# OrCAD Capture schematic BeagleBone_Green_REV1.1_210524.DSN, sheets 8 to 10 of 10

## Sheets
8 P09_10/100 Ethernet: size B; title: BeagleBone Green Ethernet
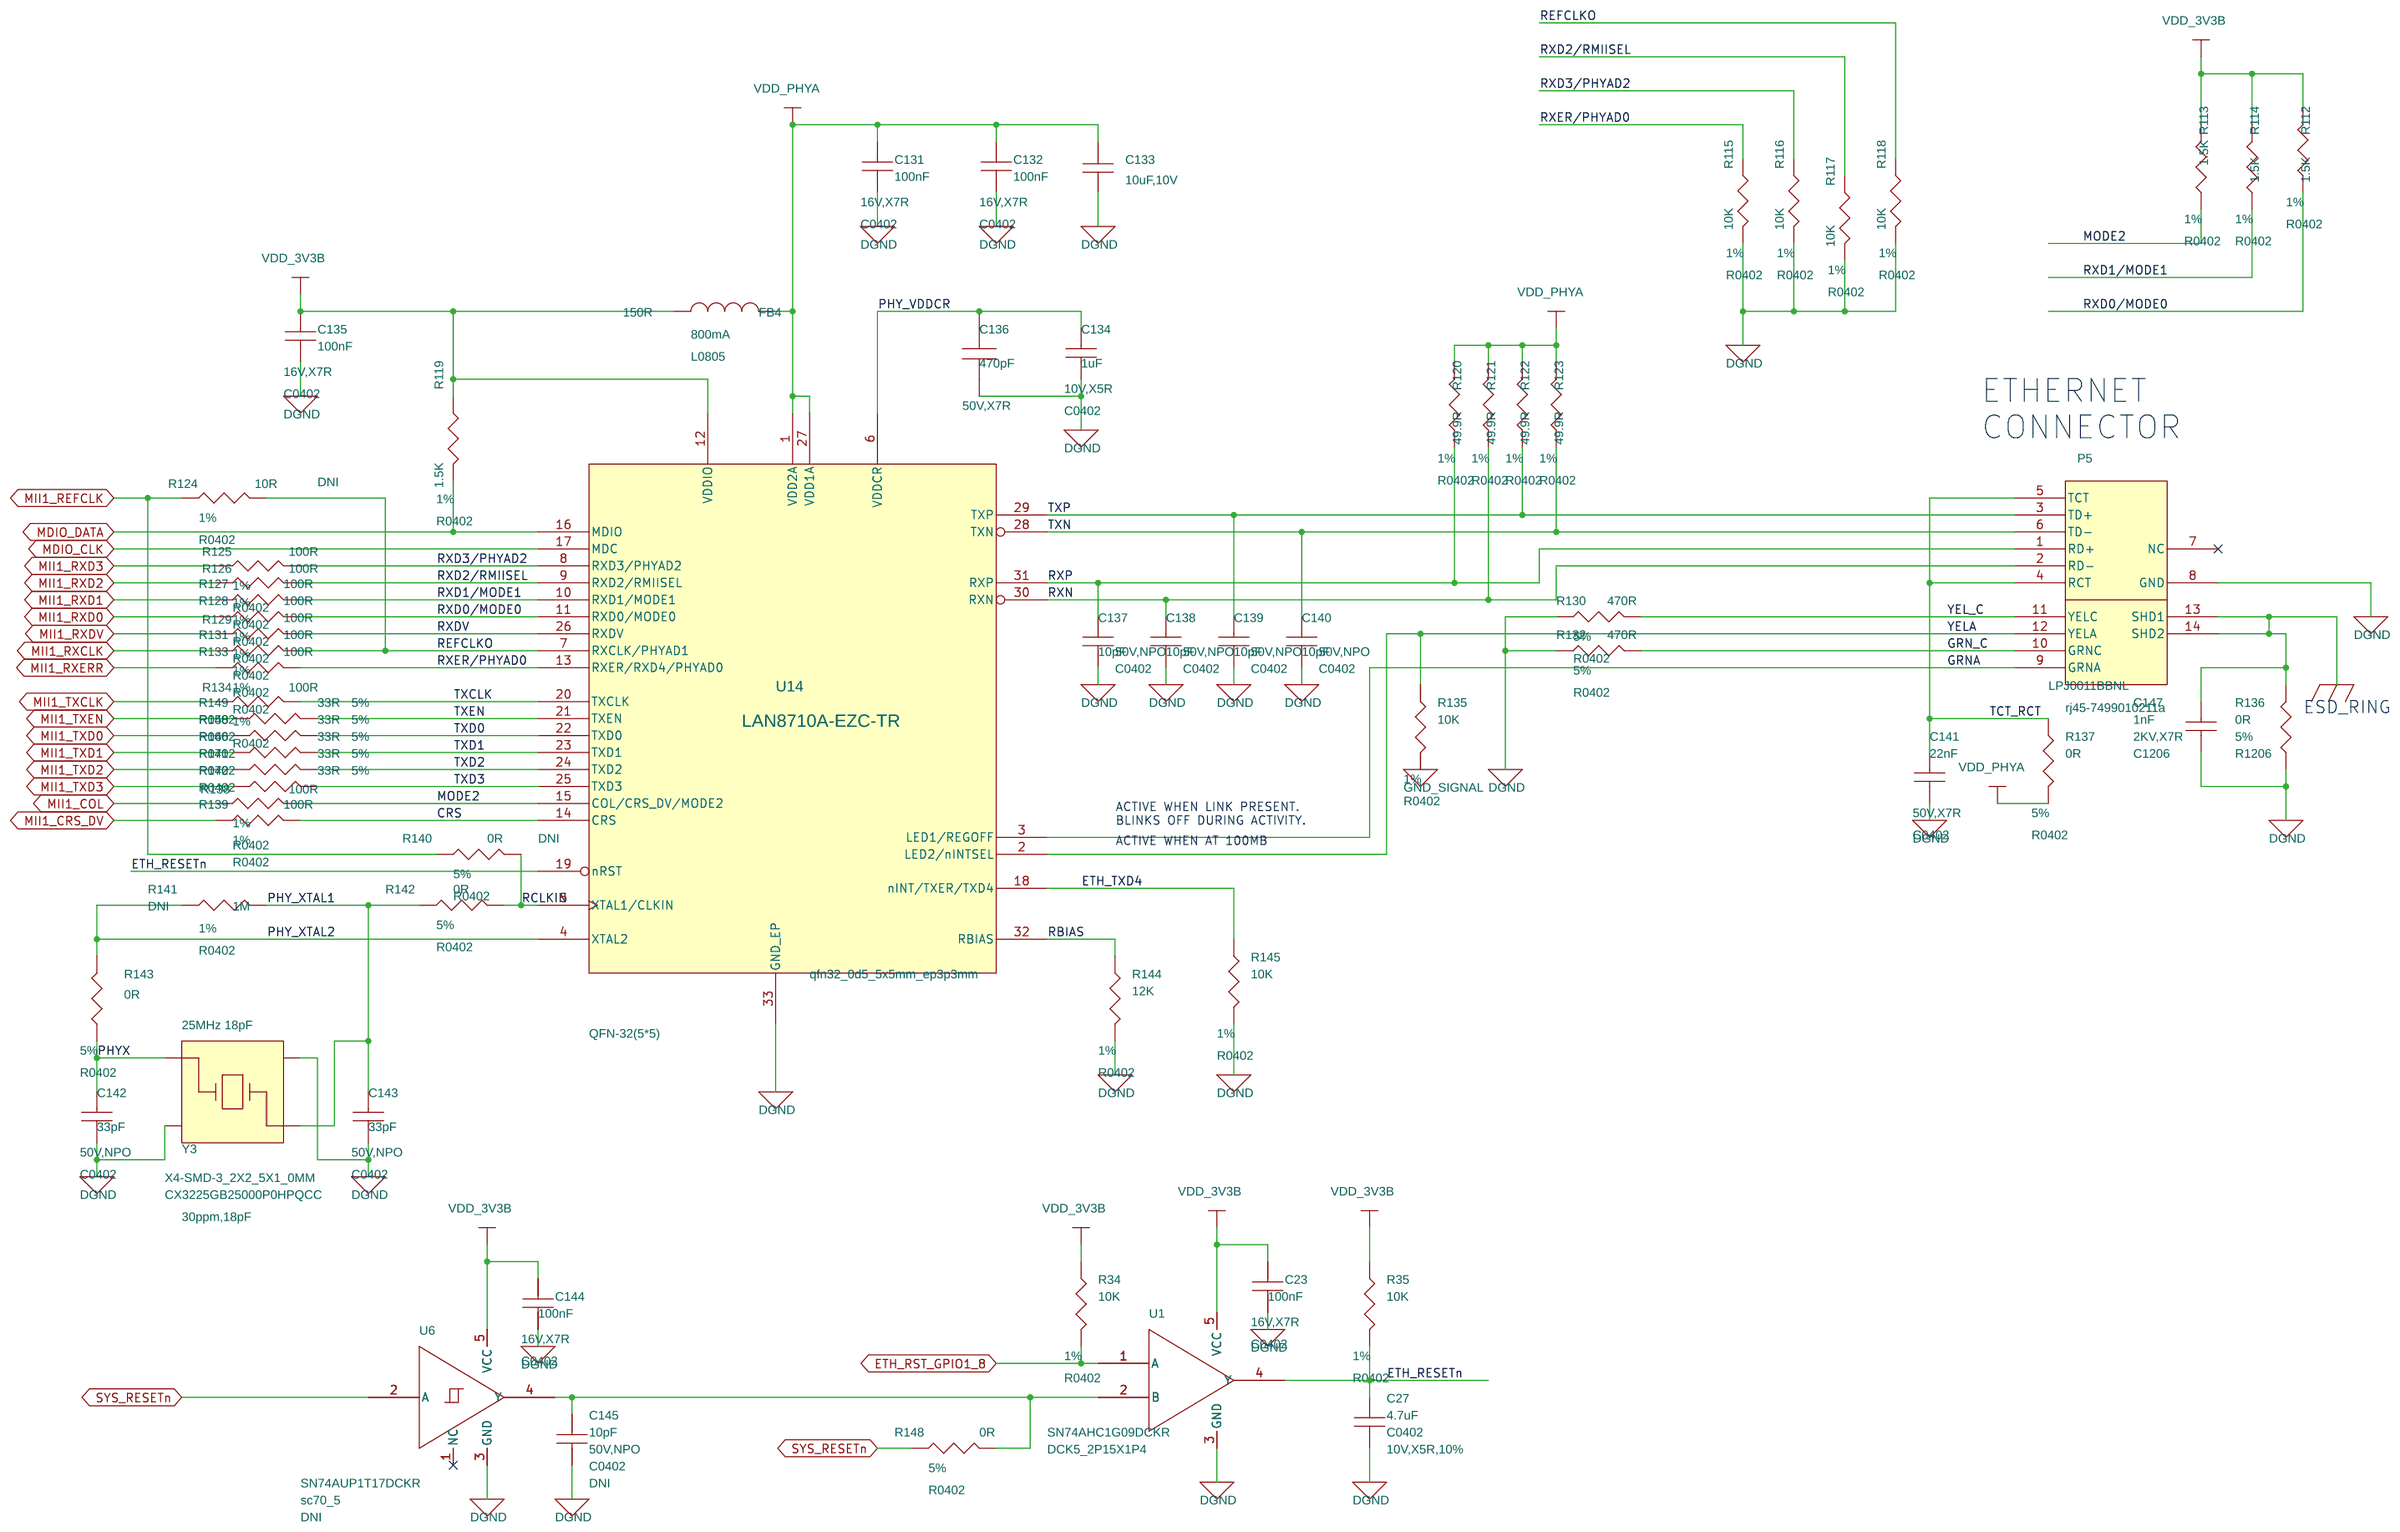
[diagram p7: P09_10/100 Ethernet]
9 P04_AM335x 2/3, USB: size C; title: BeagleBone Green Processor 2 of 3, USB,  and Serial
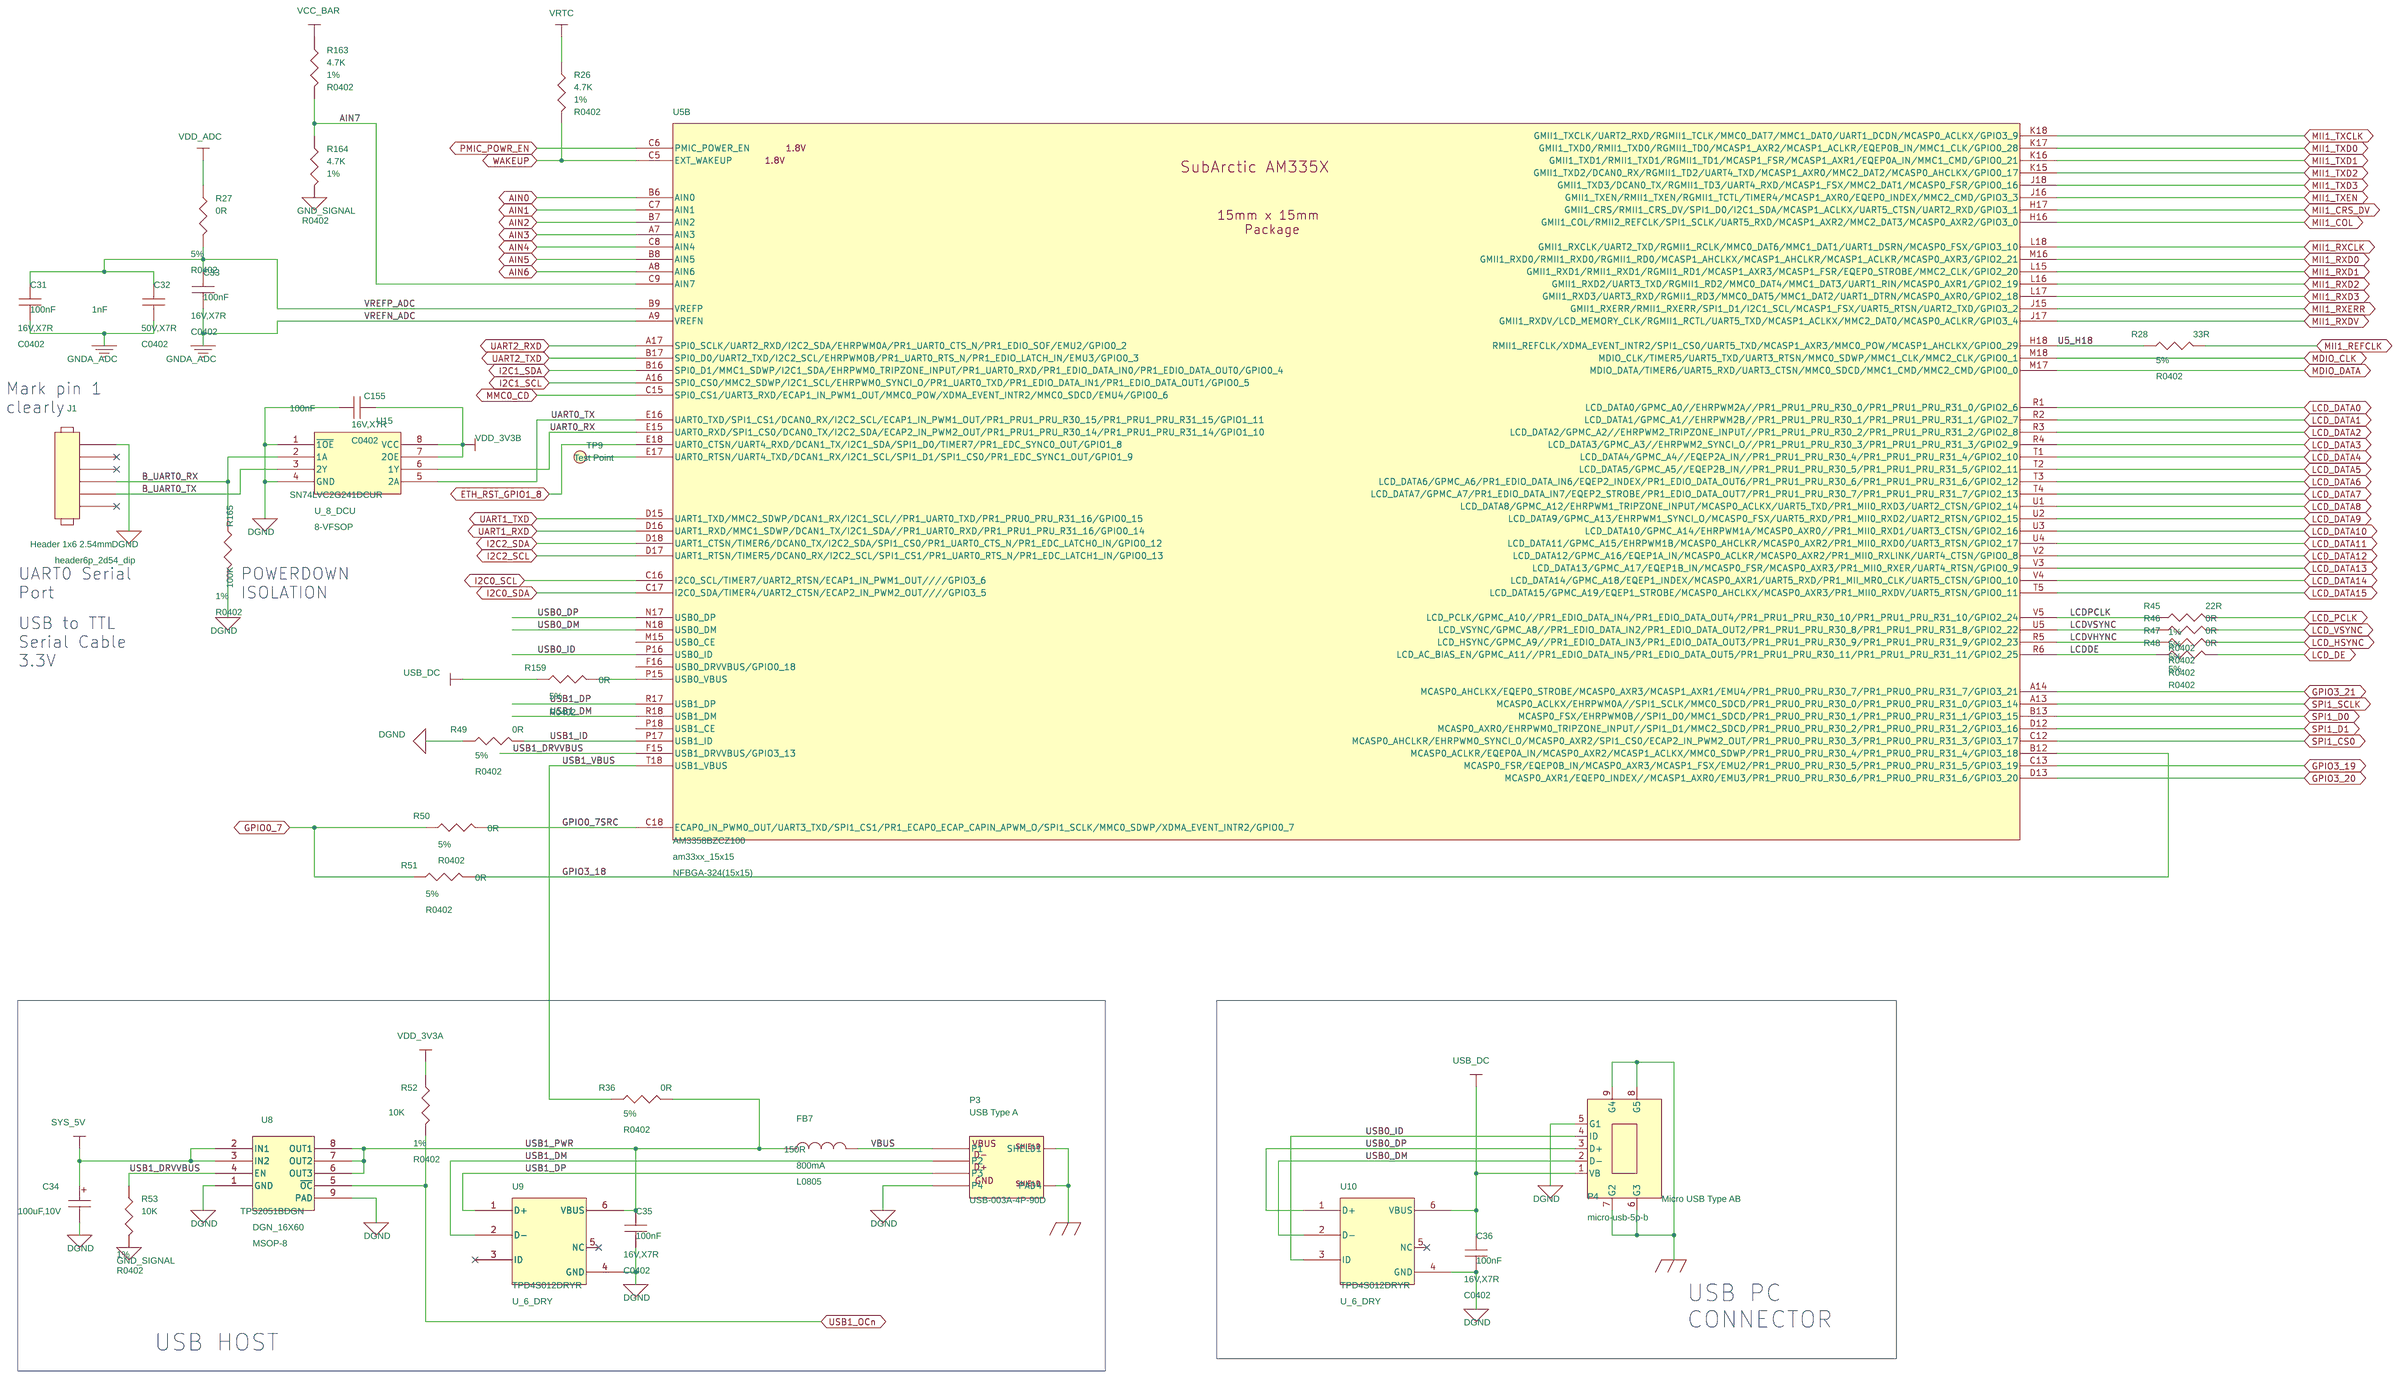
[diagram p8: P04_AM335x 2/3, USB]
10 P03_AM335x 1/3, JTAG: size C; title: BeagleBone Green Processor 1 of 3 and JTAG
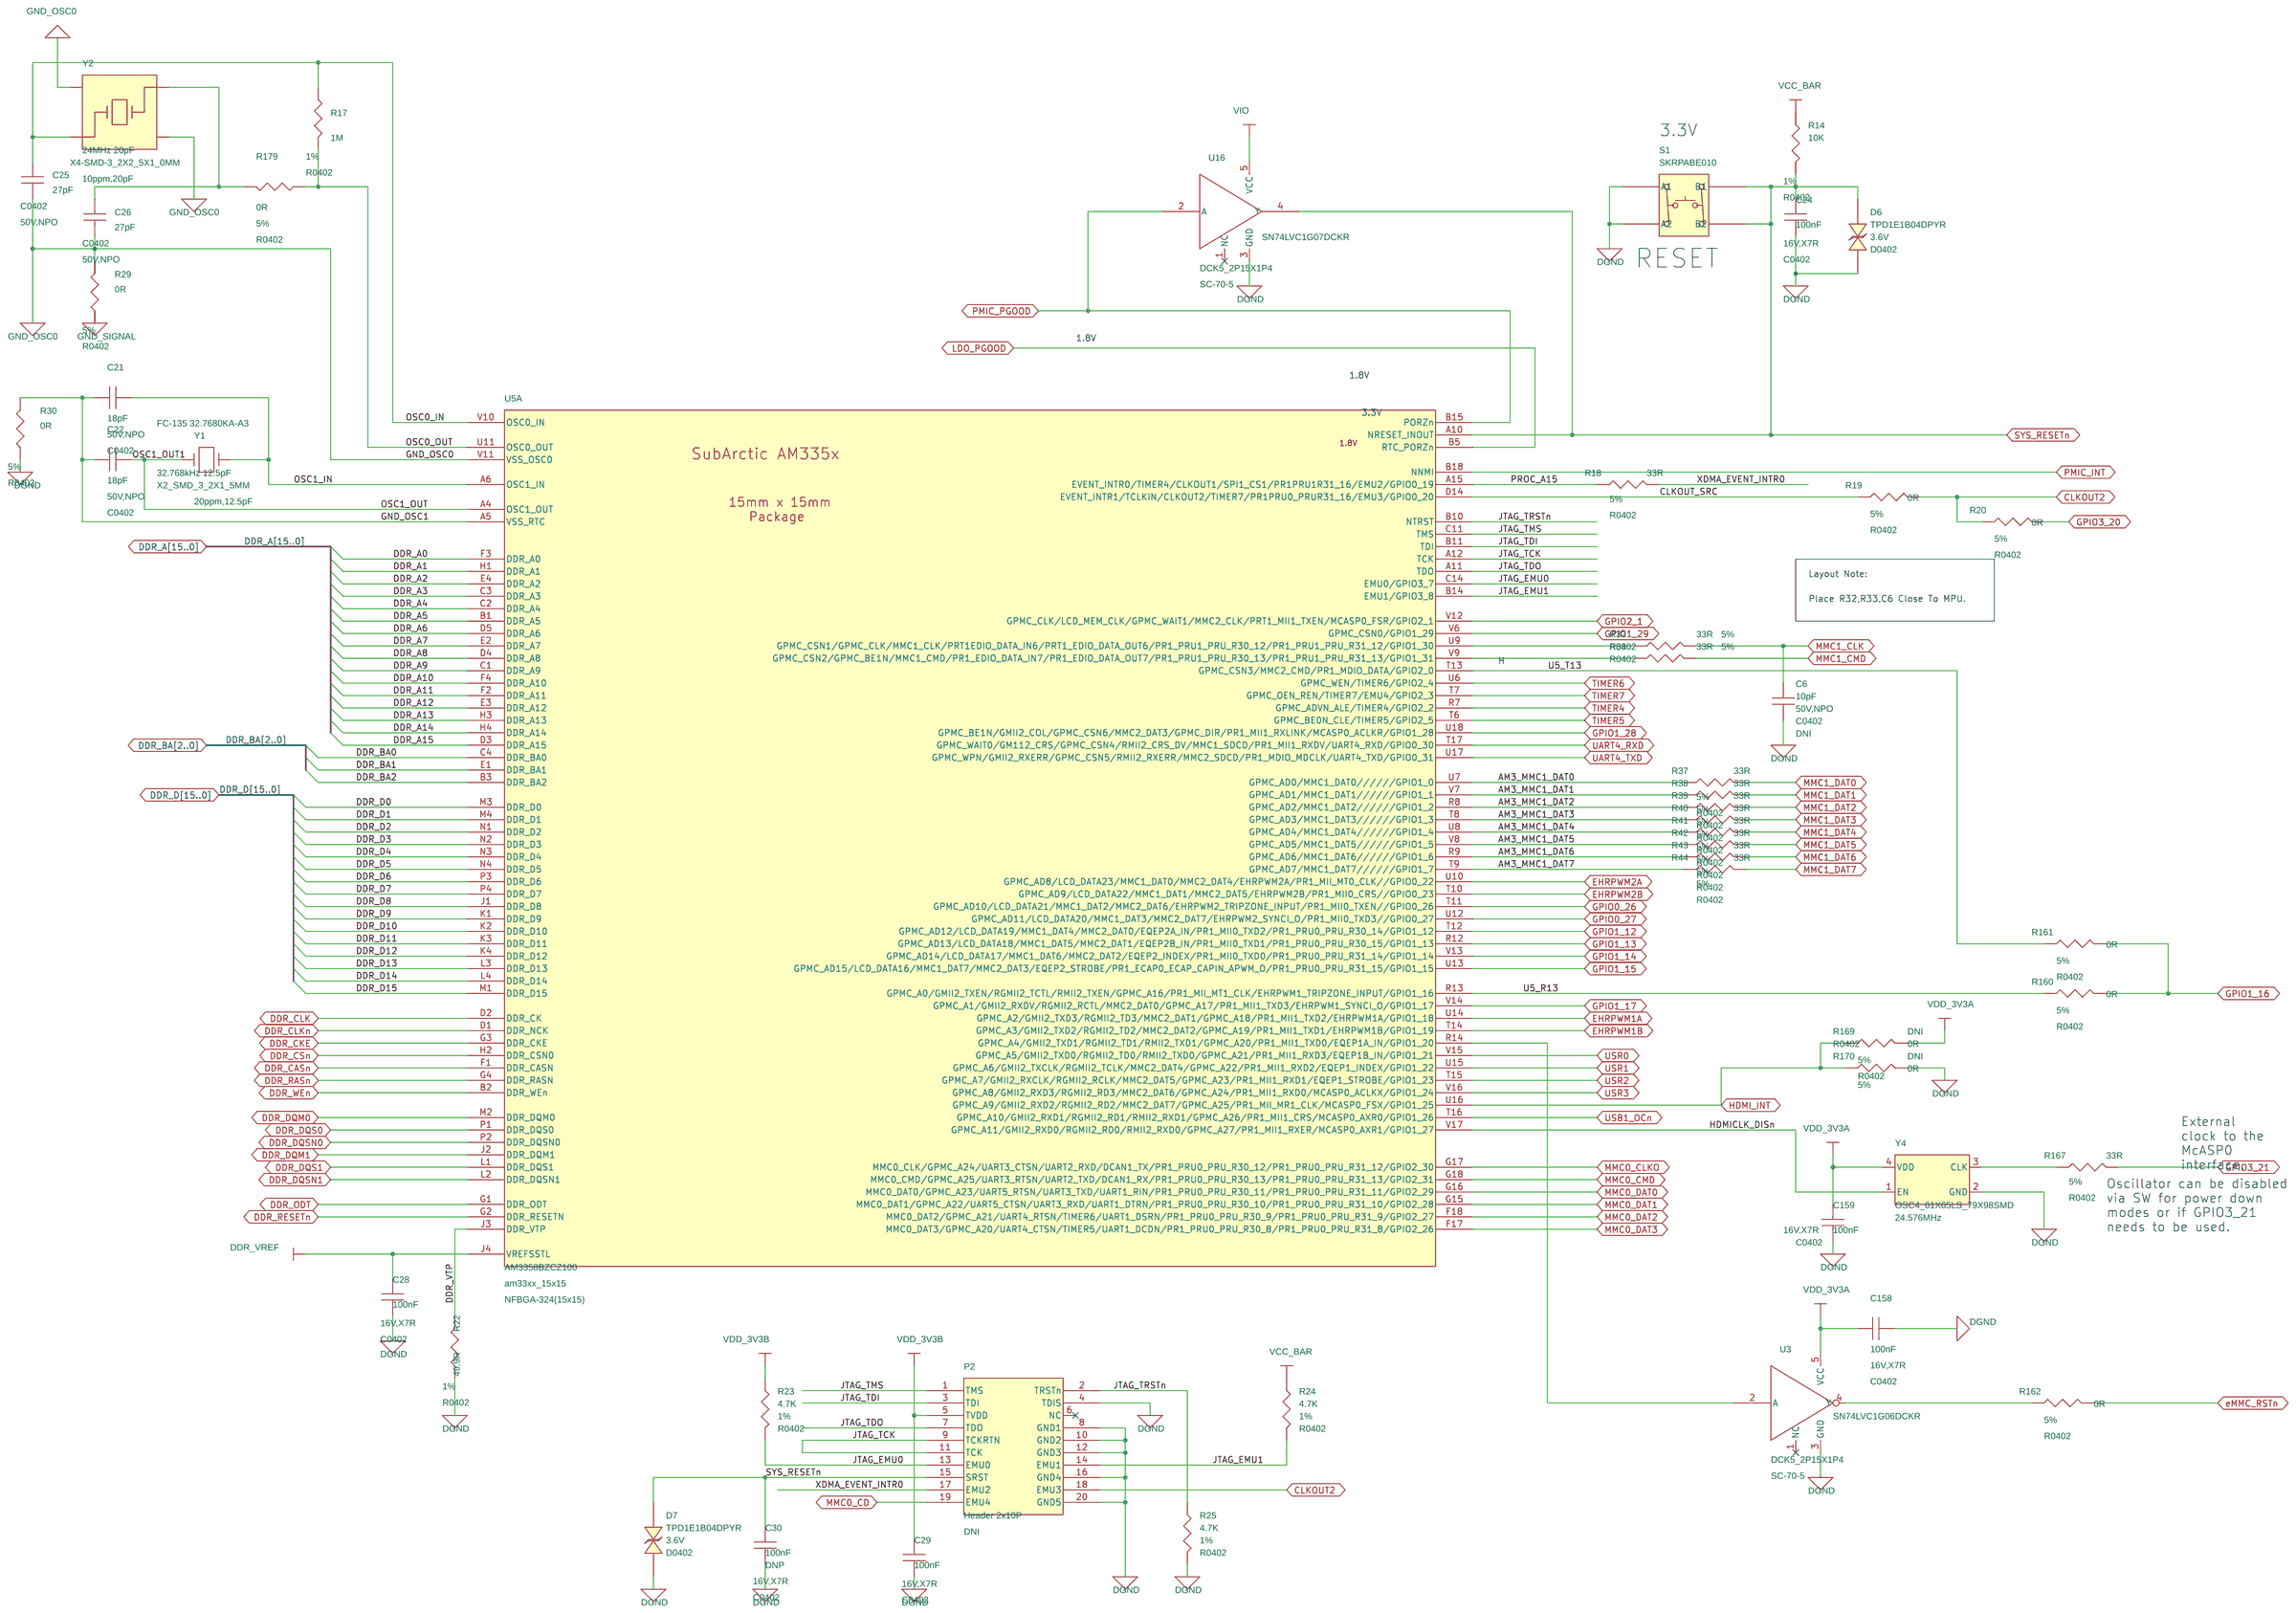
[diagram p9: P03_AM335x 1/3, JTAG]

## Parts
sheet P03_AM335x 1/3, JTAG
C6  10pF  [C0402]
C21  18pF  [C0402]
C22  18pF  [C0402]
C24  100nF  [C0402]
C25  27pF  [C0402]
C26  27pF  [C0402]
C28  100nF  [C0402]
C29  100nF  [C0402]
C30  100nF  [C0402]
C158  100nF  [C0402]
C159  100nF  [C0402]
D6  TPD1E1B04DPYR  [D0402]
D7  TPD1E1B04DPYR  [D0402]
P2  Header 2x10P  [HEADER10X2_SMD]
R14  10K  [R0402]
R17  1M  [R0402]
R18  33R  [R0402]
R19  0R  [R0402]
R20  0R  [R0402]
R22  49.9R  [R0402]
R23  4.7K  [R0402]
R24  4.7K  [R0402]
R25  4.7K  [R0402]
R29  0R  [R0402]
R30  0R  [R0402]
R32  33R  [R0402]
R33  33R  [R0402]
R37  33R  [R0402]
R38  33R  [R0402]
R39  33R  [R0402]
R40  33R  [R0402]
R41  33R  [R0402]
R42  33R  [R0402]
R43  33R  [R0402]
R44  33R  [R0402]
R160  0R  [R0402]
R161  0R  [R0402]
R162  0R  [R0402]
R167  33R  [R0402]
R169  0R  [R0402]
R170  0R  [R0402]
R179  0R  [R0402]
S1  SKRPABE010  [SW_4P]
U3  SN74LVC1G06DCKR  [DCK5_2P15X1P4]
U16  SN74LVC1G07DCKR  [DCK5_2P15X1P4]
Y1  32.768kHz 12.5pF  [X2_SMD_3_2X1_5MM]
Y2  24MHz 20pF  [X4-SMD-3_2X2_5X1_0MM]
Y4  24.576MHz  [OSC4_61X65LS_79X98SMD]
sheet P04_AM335x 2/3, USB
C31  100nF  [C0402]
C32  1nF  [C0402]
C33  100nF  [C0402]
C34  100uF,10V  [RD205SMD_250D]
C35  100nF  [C0402]
C36  100nF  [C0402]
C155  100nF  [C0402]
FB7  150R  [L0805]
J1  Header 1x6 2.54mm  [header6p_2d54_dip]
P3  USB Type A  [USB-003A-4P-90D]
P4  Micro USB Type AB  [micro-usb-5p-b]
R26  4.7K  [R0402]
R27  0R  [R0402]
R28  33R  [R0402]
R36  0R  [R0402]
R45  22R  [R0402]
R46  0R  [R0402]
R47  0R  [R0402]
R48  0R  [R0402]
R49  0R  [R0402]
R50  0R  [R0402]
R51  0R  [R0402]
R52  10K  [R0402]
R53  10K  [R0402]
R159  0R  [R0402]
R163  4.7K  [R0402]
R164  4.7K  [R0402]
R165  100K  [R0402]
TP9  Test Point  [TP60C33D]
U5  AM3358BZCZ100  [am33xx_15x15]  (sections A,B,C)
U8  TPS2051BDGN  [DGN_16X60]
U9  TPD4S012DRYR  [U_6_DRY]
U10  TPD4S012DRYR  [U_6_DRY]
U15  SN74LVC2G241DCUR  [U_8_DCU]
sheet P09_10/100 Ethernet
C23  100nF  [C0402]
C27  4.7uF  [C0402]
C131  100nF  [C0402]
C132  100nF  [C0402]
C133  10uF,10V  [805]
C134  1uF  [C0402]
C135  100nF  [C0402]
C136  470pF  [C0402]
C137  10pF  [C0402]
C138  10pF  [C0402]
C139  10pF  [C0402]
C140  10pF  [C0402]
C141  22nF  [C0402]
C142  33pF  [C0402]
C143  33pF  [C0402]
C144  100nF  [C0402]
C145  10pF  [C0402]
C147  1nF  [C1206]
FB4  150R  [L0805]
P5  LPJ0011BBNL  [rj45-7499010211a]
R34  10K  [R0402]
R35  10K  [R0402]
R112  1.5K  [R0402]
R113  1.5K  [R0402]
R114  1.5K  [R0402]
R115  10K  [R0402]
R116  10K  [R0402]
R117  10K  [R0402]
R118  10K  [R0402]
R119  1.5K  [R0402]
R120  49.9R  [R0402]
R121  49.9R  [R0402]
R122  49.9R  [R0402]
R123  49.9R  [R0402]
R124  10R  [R0402]
R125  100R  [R0402]
R126  100R  [R0402]
R127  100R  [R0402]
R128  100R  [R0402]
R129  100R  [R0402]
R130  470R  [R0402]
R131  100R  [R0402]
R132  470R  [R0402]
R133  100R  [R0402]
R134  100R  [R0402]
R135  10K  [R0402]
R136  0R  [R1206]
R137  0R  [R0402]
R138  100R  [R0402]
R139  100R  [R0402]
R140  0R  [R0402]
R141  1M  [R0402]
R142  0R  [R0402]
R143  0R  [R0402]
R144  12K  [R0402]
R145  10K  [R0402]
R148  0R  [R0402]
R149  33R  [R0402]
R158  33R  [R0402]
R166  33R  [R0402]
R171  33R  [R0402]
R172  33R  [R0402]
U1  SN74AHC1G09DCKR  [DCK5_2P15X1P4]
U6  SN74AUP1T17DCKR  [sc70_5]
U14  LAN8710A-EZC-TR  [qfn32_0d5_5x5mm_ep3p3mm]
Y3  25MHz 18pF  [X4-SMD-3_2X2_5X1_0MM]

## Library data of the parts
C6 C145 = CC: SMD CAP Ceramic 10pF-50V-5%-NPO;0402; ASSY: DNI; Manufacturer: YAGEO; Manufacturer Part Number: CC0402JRNPO9BN100; PN: 302010001; Package Size: 0402; Part Type: Ceramic; Rating: 50V,NPO; Status: BeagleBone Carrier Board; Temperature: -55°C to 125°C
C21 C22 = CAP_18PF_COG_50V_5%_0402: SMD CAP Ceramic 18pF-50V-5%-NPO;0402; Manufacturer: YAGEO; Manufacturer Part Number: CC0402JRNPO9BN180; PN: 302010016; Package Size: 0402; Part Type: Ceramic Capacitor; Rating: 50V,NPO; Status: BeagleBone Carrier Board; Temperature: -55°C to 125°C
C23 C24 C28 C29 C31 C33 C35 C36 C131 C132 C135 C144 C155 C158 C159 = CAP_0.1uF_X5R_6.3V_20%_0201: SMD CAP Ceramic 100nF-16V-10%-X7R;0402; Manufacturer: YAGEO; Manufacturer Part Number: CC0402KRX7R7BB104; PN: 302010004; Package Size: 0402; Part Type: Ceramic Capacitor; Rating: 16V,X7R; Status: BeagleBone Carrier Board; Temperature: -55°C to 125°C
C25 C26 = CC: SMD CAP Ceramic 27pF-50V-5%-NPO;0402; Manufacturer: YAGEO; Manufacturer Part Number: CC0402JRNPO9BN270; PN: 302010027; Package Size: 0402; Rating: 50V,NPO; Status: BeagleBone AI TDA4VM; Temperature: -55°C to 125°C
C30 = CAP_0.1uF_X5R_6.3V_20%_0201: SMD CAP Ceramic 100nF-16V-10%-X7R;0402; ASSY: DNP; Manufacturer: YAGEO; Manufacturer Part Number: CC0402KRX7R7BB104; PN: 302010004; Package Size: 0402; Part Type: Ceramic Capacitor; Rating: 16V,X7R; Status: BeagleBone Carrier Board; Temperature: -55°C to 125°C
D6 D7 = DIODE_TVS_BI-DIR: SMD TVS DIODE 3.6V-6.4V-1pF;X1SON(2); Manufacturer: TI; PN: 304050798; Package Size: 0402; Part Type: ESD; Rating: 3.6V; Status: Grove Base Cape for PocketBeagle; Temperature: -40°C to 125°C
P2 = HDR_10x2_CJTAG_0: SMD Black Male Header;2*10P-1.27mm; ASSY: DNI; Part Type: Male Header
R14 R34 R35 R52 R53 R135 R145 = RES_10K_1_16W_1%_0402: SMD RES 10K-1%-1/16W;0402; Manufacturer: YAGEO; Manufacturer Part Number: RC0402FR-0710KL; PN: 301010047; Package Size: 0402; Part Type: Thick Film Resistor; Rating: 1%; Status: BeagleBone Carrier Board; Temperature: -55°C to 155°C
R17 = RES_1M_1_16W_1%_0402: SMD RES 1M-1%-1/16W;0402; Manufacturer: YAGEO; Manufacturer Part Number: RC0402FR-071ML; PN: 301010043; Package Size: 0402; Part Type: Thick Film Resistor; Rating: 1%; Status: BeagleBone Carrier Board; Temperature: -55°C to 155°C
R18 R28 R167 = RES_33_0402: SMD RES 33R-5%-1/16W;0402; Manufacturer: YAGEO; Manufacturer Part Number: RC0402JR-0733RL; PN: 301010034; Package Size: 0402; Part Number: RES_33_0201; Part Type: Thick Film Resistor; Rating: 5%; Status: BeagleBone Carrier Board; Temperature: -55°C to 155°C
R19 R20 R27 R29 R30 R142 R143 R148 R179 = RES_0_1_16W_1%_0402: SMD RES 0R-5%-1/16W;0402; Manufacturer: YAGEO; Manufacturer Part Number: RC0402JR-070RL; PN: 301010000; Package Size: 0402; Part Type: Thick Film Resistor; Rating: 5%; Status: BeagleBone Carrier Board; Temperature: -55°C to 155°C
R22 R120-R123 = RES_4.7K_0402: SMD RES 49.9R-1%-1/16W;0402; Manufacturer: YAGEO; Manufacturer Part Number: RC0402FR-0749R9L; PN: 301010041; Package Size: 0402; Part Type: Thick Film Resistor; Rating: 1%; Status: BeagleBone Carrier Board; Temperature: -55°C to 155°C
R23-R26 R163 R164 = R: SMD RES;4.7K-1%-1/16W-0402; Manufacturer: YAGEO; Manufacturer Part Number: RC0402FR-074K7L; PN: 301010633; Package Size: 0402; Part Type: RES; Rating: 1%; Status: BeagleBone Carrier Board; Temperature: -55°C to 155°C
R32 R33 R149 R158 R166 R171 R172 = R: SMD RES 33R-5%-1/16W;0402; Manufacturer: YAGEO; Manufacturer Part Number: RC0402JR-0733RL; PN: 301010034; Package Size: 0402; Part Type: RES; Rating: 5%; Status: BeagleBone Carrier Board; Temperature: -55°C to 155°C
R37-R44 = RES_33_0402: SMD RES 33R-5%-1/16W;0402; Manufacturer: YAGEO; Manufacturer Part Number: RC0402JR-0733RL; PN: 301010034; Package Size: 0402; Part Type: Thick Film Resistor; Rating: 5%; Status: BeagleBone Carrier Board; Temperature: -55°C to 155°C
R50 R51 R159-R162 = RES_4.75K_1_16W_1%_0402: SMD RES 0R-5%-1/16W;0402; Manufacturer: YAGEO; Manufacturer Part Number: RC0402JR-070RL; PN: 301010000; Package Size: 0402; Part Type: Thick Film Resistor; Rating: 5%; Status: BeagleBone Carrier Board; Temperature: -55°C to 155°C
R169 R170 = RES_4.75K_1_16W_1%_0402: SMD RES 0R-5%-1/16W;0402; ASSY: DNI; Manufacturer: YAGEO; Manufacturer Part Number: RC0402JR-070RL; PN: 301010000; Package Size: 0402; Part Type: Thick Film Resistor; Rating: 5%; Status: BeagleBone Carrier Board; Temperature: -55°C to 155°C
S1 = SW_KT11P2JM_2: SMD Top Button 1.57N;4P-L4.6*W3.2*H2.5mm; Manufacturer: ALPS; PN: 311020518; Part Type: Button; Temperature: -30C to 85C
U3 = IC_SN74LVC1G06DCK_0: SMD IC Logic;SC-70-5; Manufacturer: TI; PN: 310050077; Package Size: SC-70-5; Part Type: Buffer; Status: Combox Pro; Temperature: -40°C to 125°C
U16 = IC_SN74LVC1G07DCK: SMD IC Logic;Single Buffer/Driver With Open-Drain Output;SC-70-5; Manufacturer: TI; PN: 310050079; Package Size: SC-70-5; Part Type: Buffer; Status: BeagleBone Carrier Board; Temperature: -40°C to 125°C
Y1 = XTAL_2P: SMD Crystal 32.768KHz-12.5pF-20ppm-2P-3.2*1.5*0.9mm; Manufacturer: EPSON; Manufacturer Part Number: FC-135 32.7680KA-A3; PN: 306010138; Package Size: 3.2x1.5x0.9mm; Part Type: Crystal; Rating: 20ppm,12.5pF; Status: BeagleBone Carrier Board; Temperature: -40°C to 85°C
Y2 = XTAL_4P: SMD Crystal 24MHz-20pF-10ppm;4P-SMD-L3.2*W2.5*H0.7mm; Manufacturer: ECEC; Manufacturer Part Number: M24000J407; PN: 306011544; Package Size: 3.2x2.5x0.7mm; Part Type: Crystal; Rating: 10ppm,20pF; Status: J40 MINI AI BOX; Temperature: -40°C to 85°C
Y4 = OSC_4P: SMD Oscillator;24.576MHz-50ppm-3.3V-4P-2.5*2*1mm; Manufacturer: ECEC; Manufacturer Part Number: DS24576007; PN: 306020923; Package Size: 2.5x2x1mm; Status: reTerminal DM; Temperature: -40°C to 85°C
C32 = CAP_0.001_X7R_50V_5%_0402: SMD CAP Ceramic 1nF-50V-10%-X7R;0402; Manufacturer: YAGEO; Manufacturer Part Number: CC0402KRX7R9BB102; PN: 302010005; Package Size: 0402; Part Type: Ceramic Capacitor; Rating: 50V,X7R; Status: RT-M7; Temperature: -55°C to 125°C
C34 = CAP_100UF_TANT_6.3V_3528-21: SMD CAP Aluminum 100uF-10V;D6.3*H5.4mm; Manufacturer: ST; Manufacturer Part Number: CS1A101M-CRE54; PN: 302030050; Part Type: Aluminum Capacitor; Rating: 10V; Temperature: -40C to 105C
FB4 FB7 = FER_180_200_0: SMD Ferrite Bead;150R-800mA-0805; Manufacturer: LAIRD; Manufacturer Part Number: LI0805H151R-10; PN: 303030029; Package Size: 0805; Part Type: Ferrite Bead; Rating: 800mA; Status: BeagleBone Green Gateway; Temperature: -40°C to 125°C
J1 = HEADER_6: DIP Black Male Header VERT;1*6P-2.54-2.54-11.6/3.0mm; Manufacturer: 思拓展; Manufacturer Part Number: ST-PH-254-0087-1*6P-6T; PN: 320020078; Package Size: 1*6P-2.54-2.54-11.6/3.0mm; Part Type: Header; Status: BeagleBone Carrier Board
P3 = CONN_54819-0578_2: DIP USB A TYPE FMAL;4P-2.0-90D; Manufacturer: SUNGTECH; Manufacturer Part Number: ST-USB-003A; PN: 320010007; Package Size: 4P-2.0-90D; Status: BeagleBone Green Gateway
P4 = MINI-USB-AB-SOCKET: SMD Micro USB-B-without POST-W/P;5+4P-0.65-L7.4*W5.0*H2.35mm; Manufacturer: 商祺; Manufacturer Part Number: ST-USB-001G; PN: 320010000; Package Size: 5P+6; Part Type: USB Mini B; Status: J40 MINI AI BOX; Temperature: -30°C to 80°C
R36 R49 = RES_100K_1_16W_1%_0402: SMD RES 0R-5%-1/16W;0402; Manufacturer: YAGEO; Manufacturer Part Number: RC0402JR-070RL; PN: 301010000; Package Size: 0402; Part Type: Thick Film Resistor; Rating: 5%; Status: BeagleBone Carrier Board; Temperature: -55°C to 155°C
R45 = RES_33_0402: SMD RES 22R-1%-1/16W;0402; Manufacturer: YAGEO; Manufacturer Part Number: RC0402FR-0722RL; PN: 301010052; Package Size: 0402; Part Number: RES_33_0201; Part Type: Thick Film Resistor; Rating: 1%; Status: BeagleBone Carrier Board; Temperature: -55°C to 155°C
R46-R48 = RES_33_0402: SMD RES 0R-5%-1/16W;0402; Manufacturer: YAGEO; Manufacturer Part Number: RC0402JR-070RL; PN: 301010000; Package Size: 0402; Part Number: RES_33_0201; Part Type: Thick Film Resistor; Rating: 5%; Status: BeagleBone Carrier Board; Temperature: -55°C to 155°C
R165 = RES_100K_1_16W_1%_0402: SMD RES 100K-1%-1/16W;0402; Manufacturer: YAGEO; Manufacturer Part Number: RC0402FR-07100KL; PN: 301010456; Package Size: 0402; Part Type: Thick Film Resistor; Rating: 1%; Status: BeagleBone Carrier Board; Temperature: -55°C to 155°C
TP9 = TESTPT1: DIP Test Point,35mil,60mil; ASSY: DNI
U5 = IC_AM335X_ZCZ: SMD IC MCU;NFBGA-324（15x15）; Manufacturer: TI; PN: 310010099; Package Size: NFBGA-324(15x15); Part Type: MPU; Status: Combox Pro; Temperature: 0°C to 90°C
U8 = TPS2061_1: SMD IC PMIC;MSOP-8; Manufacturer: TI; Manufacturer Part Number: TPS2051BDGNR; PN: 310030211; Package Size: MSOP-8; Part Type: Power Switch; Status: BeagleBone Green Gateway; Temperature: -40°C to 85°C
U9 U10 = PROT_TPD4S012: SMD Diode TVS 4-Ch USB ESD Solution with;SON-6(1.45x1); Manufacturer: TI; PN: 304050020; Package Size: SON-6(1.45x1); Part Type: Diode TVS; Status: BeagleBone Carrier Board; Temperature: -40°C to 85°C
U15 = IC_SN74LVC2G241_1: SMD IC Logic;Dual Buffer/Driver With 3-State Outputs;US8(8-VFSOP); Manufacturer: TI; PN: 310050078; Package Size: 8-VFSOP; Part Type: Buffer; Status: BeagleBone Carrier Board; Temperature: -40°C to 125°C
C27 = CC: SMD CAP Ceramic 4.7uF-10V-10%-X5R;0402; Manufacturer: YAGEO; Manufacturer Part Number: CC0402KRX5R6BB475; PN: 302010407; Package Size: 0402; Part Type: Ceramic; Rating: 10V,X5R,10%; Status: BBG; Temperature: -55°C to 85°C
C133 = CAP_10uF_Y5V_10V_10%_0805: SMD CAP Ceramic 10uF-10V-(-20%~+80%)-Y5V;0805; Manufacturer: YAGEO; Manufacturer Part Number: CC0805ZKY5V6BB106; PN: 302010158; Part Type: Ceramic Capacitor; Rating: 10V,Y5V; Temperature: -30C to 85C
C134 = CAP_1.0UF_X5R_10V_10%_0402: SMD CAP Ceramic 1uF-10V-10%-X5R;0402; Manufacturer: YAGEO; Manufacturer Part Number: CC0402KRX5R6BB105; PN: 302010040; Package Size: 0402; Part Type: Ceramic Capacitor; Rating: 10V,X5R; Status: BeagleBone Carrier Board; Temperature: -55°C to 85°C
C136 = 470pF_5%_50V_C0G_0603_0: SMD CAP Ceramic 470pF-50V-10%-X7R;0402; Manufacturer: YAGEO; Manufacturer Part Number: CC0402KRX7R9BB471; PN: 302010010; Package Size: 0402; Part Type: Ceramic Capacitor; Rating: 50V,X7R; Status: Mini-Gateway; Temperature: -55°C to 125°C
C137-C140 = CC: SMD CAP Ceramic 10pF-50V-5%-NPO;0402; Manufacturer: YAGEO; Manufacturer Part Number: CC0402JRNPO9BN100; PN: 302010001; Package Size: 0402; Part Type: Ceramic; Rating: 50V,NPO; Status: BeagleBone Carrier Board; Temperature: -55°C to 125°C
C141 = CAP_0402_0.1uf_X5R_10V: SMD CAP Ceramic 22nF-50V-10%-X7R;0402; Manufacturer: YAGEO; Manufacturer Part Number: CC0402KRX7R9BB223; PN: 302010242; Package Size: 0402; Part Type: Ceramic Capacitor; Rating: 50V,X7R; Status: ST; Temperature: -55°C to 125°C
C142 C143 = CAP_30PF_COG_50V_5%_0402: SMD CAP Ceramic 33pF-50V-5%-NPO;0402; Manufacturer: YAGEO; Manufacturer Part Number: CC0402JRNPO9BN330; PN: 302010000; Package Size: 0402; Part Type: Ceramic Capacitor; Rating: 50V,NPO; Status: Mini-Gateway; Temperature: -55°C to 125°C
C147 = CC: SMD CAP Ceramic 1nF-2kV-10%-X7R;1206; Manufacturer: YAGEO; Manufacturer Part Number: CC1206KKX7RDBB102; PN: 302011962; Package Size: 1206; Part Type: Ceramic; Rating: 2KV,X7R; Status: Zola_Gateway; Temperature: -55°C to 125°C
P5 = CONN_RJ45_MAG_WE_0: DIP RJ45 W/P-10/100M;12P-21.25*15.93*13.3mm; Manufacturer: Link-PP; PN: 320140216; Part Type: RJ45; Status: Zola; Temperature: 0°C to 70°C
R112-R114 = RES_4.75K_1_16W_1%_0402: SMD RES 1.5K-1%-1/16W;0402; Manufacturer: YAGEO; Manufacturer Part Number: RC0402FR-071K5L; PN: 301010567; Package Size: 0402; Part Type: Thick Film Resistor; Rating: 1%; Status: BeagleBone Carrier Board; Temperature: -55°C to 155°C
R115-R118 = RES_4.75K_1_16W_1%_0402: SMD RES 10K-1%-1/16W;0402; Manufacturer: YAGEO; Manufacturer Part Number: RC0402FR-0710KL; PN: 301010047; Package Size: 0402; Part Type: Thick Film Resistor; Rating: 1%; Status: BeagleBone Carrier Board; Temperature: -55°C to 155°C
R119 = RES_1.5K_1_16W_5%_0402: SMD RES 1.5K-1%-1/16W;0402; Manufacturer: YAGEO; Manufacturer Part Number: RC0402FR-071K5L; PN: 301010567; Package Size: 0402; Part Type: Thick Film Resistor; Rating: 1%; Status: BeagleBone Carrier Board; Temperature: -55°C to 155°C
R124 = 100-1_10W-1%-0603_4: SMD RES 10R-1%-1/16W;0402; ASSY: DNI; Manufacturer: YAGEO; Manufacturer Part Number: RC0402FR-0710RL; PN: 301010444; Package Size: 0402; Part Type: Thick Film Resistor; Rating: 1%; Status: IOT Enabling Dongle Board; Temperature: -55°C to 155°C
R125 R126 R129 R134 R138 = 100-1_10W-1%-0603_4: SMD RES 100R-1%-1/16W;0402; Manufacturer: YAGEO; Manufacturer Part Number: RC0402FR-07100RL; PN: 301010442; Package Size: 0402; Part Type: Thick Film Resistor; Rating: 1%; Status: BeagleBone Carrier Board; Temperature: -55°C to 155°C
R127 R128 R131 R133 R139 = RES_100_1_10W_5%_0402: SMD RES 100R-1%-1/16W;0402; Manufacturer: YAGEO; Manufacturer Part Number: RC0402FR-07100RL; PN: 301010442; Package Size: 0402; Part Type: Thick Film Resistor; Rating: 1%; Status: BeagleBone Carrier Board; Temperature: -55°C to 155°C
R130 R132 = RES_470_1_10W_5%_0402: SMD RES 470R-5%-1/16W;0402; Manufacturer: YAGEO; Manufacturer Part Number: RC0402JR-07470RL; PN: 301010013; Package Size: 0402; Part Type: Thick Film Resistor; Rating: 5%; Status: BeagleBone AI TDA4VM; Temperature: -55°C to 155°C
R136 = R: SMD RES 0R-5%-1/4W;1206; Manufacturer: YAGEO; Manufacturer Part Number: RC1206JR-070RL; PN: 301010407; Package Size: 1206; Part Type: RES; Rating: 5%; Status: BeagleBone Carrier Board; Temperature: -55°C to 155°C
R137 = RES_10K_1_16W_1%_0402: SMD RES 0R-5%-1/16W;0402; Manufacturer: YAGEO; Manufacturer Part Number: RC0402JR-070RL; PN: 301010000; Package Size: 0402; Part Type: Thick Film Resistor; Rating: 5%; Status: BeagleBone Carrier Board; Temperature: -55°C to 155°C
R140 = RES_0_1_16W_1%_0402: SMD RES 0R-5%-1/16W;0402; ASSY: DNI; Manufacturer: YAGEO; Manufacturer Part Number: RC0402JR-070RL; PN: 301010000; Package Size: 0402; Part Type: Thick Film Resistor; Rating: 5%; Status: BeagleBone Carrier Board; Temperature: -55°C to 155°C
R141 = RES_1M_1_16W_1%_0402: SMD RES 1M-1%-1/16W;0402; ASSY: DNI; Manufacturer: YAGEO; Manufacturer Part Number: RC0402FR-071ML; PN: 301010043; Package Size: 0402; Part Type: Thick Film Resistor; Rating: 1%; Status: BeagleBone Carrier Board; Temperature: -55°C to 155°C
R144 = RES_12.1K_1_16W_1%_0402: SMD RES 12K-1%-1/16W;0402; Manufacturer: YAGEO; Manufacturer Part Number: RC0402FR-0712KL; PN: 301010736; Package Size: 0402; Part Type: Thick Film Resistor; Rating: 1%; Status: BeagleBone Carrier Board; Temperature: -55°C to 155°C
U1 = SN74LVC1G08DCKR: SMD IC Logic;Single 2¨CInput Positive-AND Gate With Open-Drain Output;SC-70-5; Manufacturer: TI; PN: 310051111; Part Type: Buffer; Status: BBG; Temperature: -55°C to 125°C
U6 = SN74AUP1T17DCKR: ASSY: DNI; Manufacturer: TI; Part Type: Buffer; Status: BBG; Temperature: -40°C to 85°C
U14 = LAN8710_QFN32_1: SMD IC Interface;QFN-32（5*5）; Manufacturer: Microchip; PN: 310070043; Package Size: QFN-32(5*5); Part Type: ETH PHY; Status: Mini-Gateway; Temperature: 0°C to 85°C
Y3 = XTAL_4P: SMD Crystal 25MHz-18pF-30ppm;4P-SMD-L3.2*W2.5*H0.8mm; Manufacturer: Kyocera; Manufacturer Part Number: CX3225GB25000P0HPQCC; PN: 306010744; Package Size: 3.2x2.5x0.8mm; Part Type: Crystal; Rating: 30ppm,18pF; Status: Combox Pro; Temperature: -40°C to 85°C

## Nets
DGND: C6.2 C23.2 C24.2 C27.2 C28.2 C29.2 C30.2 C34.2 C35.2 C36.2 C131.2 C132.2 C133.1 C134.2 C135.2 C136.2 C137.2 C138.2 C139.2 C140.2 C141.2 C142.2 C143.2 C144.2 C145.2 C147.2 C155.1 C158.2 C159.2 D6.1 D7.1 J1.1 P2.4(TDIS) P2.8(GND1) P2.10(GND2) P2.12(GND3) P2.16(GND4) P2.20(GND5) P3.4(P4) P4.5(G1) P5.8(GND) R22.1 R25.2 R29.1 R30.1 R49.1 R53.2 R115.2 R116.2 R117.2 R118.2 R130.1 R132.1 R135.2 R136.1 R144.2 R145.2 R164.2 R165.2 R170.2 S1.1(A1) S1.3(A2) U1.3(GND) U3.3(GND) U6.3(GND) U8.1(GND) U8.9(PAD) U9.4(GND) U10.4(GND) U14.33(GND_EP) U15.1(~{1OE}) U15.4(GND) U16.3(GND) Y3.2 Y3.4 Y4.2(GND) ; also on sheet 2 3 4 5 6 7
GND_EARTH: C147.1 P3.5(SHELD1) P3.6(PAD4) P4.6(G3) P4.7(G2) P4.8(G5) P4.9(G4) P5.13(SHD1) P5.14(SHD2) R136.2 ; also on sheet 2 6
GND_OSC0: C25.2 C26.2 R29.2 U5.V11(VSS_OSC0) Y2.2 Y2.4
GND_OSC1: C21.1 C22.1 R30.2 U5.A5(VSS_RTC)
GNDA_ADC: C31.2 C32.2 C33.2 U5.A9(VREFN) ; also on sheet 6 7
VBUS: FB7.2 P3.1(P1)
VDD_3V3A: C158.1 C159.1 R14.1 R52.1 R169.2 U3.5(VCC) Y4.4(VDD) ; also on sheet 2 3 6 7
VDD_3V3B: C23.1 C29.1 C135.1 C144.1 C155.2 FB4.1 P2.5(TVDD) R23.1 R24.1 R34.1 R35.1 R112.2 R113.2 R114.2 R119.1 R163.1 U1.5(VCC) U6.5(VCC) U14.12(VDDIO) U15.7(2OE) U15.8(VCC) ; also on sheet 2 5 6
VDD_ADC: R27.1 ; also on sheet 6 7
VDD_PHYA: C131.1 C132.1 C133.2 FB4.2 R120.2 R121.2 R122.2 R123.2 R137.2 U14.1(VDD2A) U14.27(VDD1A)
AIN0: U5.B6(AIN0) ; also on sheet 6
AIN1: U5.C7(AIN1) ; also on sheet 6
AIN2: U5.B7(AIN2) ; also on sheet 6
AIN3: U5.A7(AIN3) ; also on sheet 6
AIN4: U5.C8(AIN4) ; also on sheet 6
AIN5: U5.B8(AIN5) ; also on sheet 6
AIN6: U5.A8(AIN6) ; also on sheet 6
AIN7: R163.2 R164.1 U5.C9(AIN7)
AM3_MMC1_DAT0: R37.1 U5.U7(GPMC_AD0/MMC1_DAT0//////GPIO1_0)
AM3_MMC1_DAT1: R38.1 U5.V7(GPMC_AD1/MMC1_DAT1//////GPIO1_1)
AM3_MMC1_DAT2: R39.1 U5.R8(GPMC_AD2/MMC1_DAT2//////GPIO1_2)
AM3_MMC1_DAT3: R40.1 U5.T8(GPMC_AD3/MMC1_DAT3//////GPIO1_3)
AM3_MMC1_DAT4: R41.1 U5.U8(GPMC_AD4/MMC1_DAT4//////GPIO1_4)
AM3_MMC1_DAT5: R42.1 U5.V8(GPMC_AD5/MMC1_DAT5//////GPIO1_5)
AM3_MMC1_DAT6: R43.1 U5.R9(GPMC_AD6/MMC1_DAT6//////GPIO1_6)
AM3_MMC1_DAT7: R44.1 U5.T9(GPMC_AD7/MMC1_DAT7//////GPIO1_7)
B_UART0_RX: J1.4 R165.1 U15.2(1A)
B_UART0_TX: J1.5 U15.3(2Y)
CLKOUT2: P2.18(EMU3) R19.2 R20.1 ; also on sheet 6
CLKOUT_SRC: R19.1 U5.D14(EVENT_INTR1/TCLKIN/CLKOUT2/TIMER7/PR1PRU0_PRUR31_16/EMU3/GPIO0_20)
CRS: R139.2 U14.14(CRS)
DDR_A0: U5.F3(DDR_A0) ; also on sheet 4
DDR_A1: U5.H1(DDR_A1) ; also on sheet 4
DDR_A2: U5.E4(DDR_A2) ; also on sheet 4
DDR_A3: U5.C3(DDR_A3) ; also on sheet 4
DDR_A4: U5.C2(DDR_A4) ; also on sheet 4
DDR_A5: U5.B1(DDR_A5) ; also on sheet 4
DDR_A6: U5.D5(DDR_A6) ; also on sheet 4
DDR_A7: U5.E2(DDR_A7) ; also on sheet 4
DDR_A8: U5.D4(DDR_A8) ; also on sheet 4
DDR_A9: U5.C1(DDR_A9) ; also on sheet 4
DDR_A10: U5.F4(DDR_A10) ; also on sheet 4
DDR_A11: U5.F2(DDR_A11) ; also on sheet 4
DDR_A12: U5.E3(DDR_A12) ; also on sheet 4
DDR_A13: U5.H3(DDR_A13) ; also on sheet 4
DDR_A14: U5.H4(DDR_A14) ; also on sheet 4
DDR_A15: U5.D3(DDR_A15) ; also on sheet 4
DDR_BA0: U5.C4(DDR_BA0) ; also on sheet 4
DDR_BA1: U5.E1(DDR_BA1) ; also on sheet 4
DDR_BA2: U5.B3(DDR_BA2) ; also on sheet 4
DDR_CASn: U5.F1(DDR_CASN) ; also on sheet 4
DDR_CKE: U5.G3(DDR_CKE) ; also on sheet 4
DDR_CLK: U5.D2(DDR_CK) ; also on sheet 4
DDR_CLKn: U5.D1(DDR_NCK) ; also on sheet 4
DDR_CSn: U5.H2(DDR_CSN0) ; also on sheet 4
DDR_D0: U5.M3(DDR_D0) ; also on sheet 4
DDR_D1: U5.M4(DDR_D1) ; also on sheet 4
DDR_D2: U5.N1(DDR_D2) ; also on sheet 4
DDR_D3: U5.N2(DDR_D3) ; also on sheet 4
DDR_D4: U5.N3(DDR_D4) ; also on sheet 4
DDR_D5: U5.N4(DDR_D5) ; also on sheet 4
DDR_D6: U5.P3(DDR_D6) ; also on sheet 4
DDR_D7: U5.P4(DDR_D7) ; also on sheet 4
DDR_D8: U5.J1(DDR_D8) ; also on sheet 4
DDR_D9: U5.K1(DDR_D9) ; also on sheet 4
DDR_D10: U5.K2(DDR_D10) ; also on sheet 4
DDR_D11: U5.K3(DDR_D11) ; also on sheet 4
DDR_D12: U5.K4(DDR_D12) ; also on sheet 4
DDR_D13: U5.L3(DDR_D13) ; also on sheet 4
DDR_D14: U5.L4(DDR_D14) ; also on sheet 4
DDR_D15: U5.M1(DDR_D15) ; also on sheet 4
DDR_DQM0: U5.M2(DDR_DQM0) ; also on sheet 4
DDR_DQM1: U5.J2(DDR_DQM1) ; also on sheet 4
DDR_DQS0: U5.P1(DDR_DQS0) ; also on sheet 4
DDR_DQS1: U5.L1(DDR_DQS1) ; also on sheet 4
DDR_DQSN0: U5.P2(DDR_DQSN0) ; also on sheet 4
DDR_DQSN1: U5.L2(DDR_DQSN1) ; also on sheet 4
DDR_ODT: U5.G1(DDR_ODT) ; also on sheet 4
DDR_RASn: U5.G4(DDR_RASN) ; also on sheet 4
DDR_RESETn: U5.G2(DDR_RESETN) ; also on sheet 4
DDR_VREF: C28.1 U5.J4(VREFSSTL) ; also on sheet 4
DDR_VTP: R22.2 U5.J3(DDR_VTP)
DDR_WEn: U5.B2(DDR_WEn) ; also on sheet 4
EHRPWM1A: U5.U14(GPMC_A2/GMII2_TXD3/RGMII2_TD3/MMC2_DAT1/GPMC_A18/PR1_MII1_TXD2/EHRPWM1A/GPIO1_18) ; also on sheet 6
EHRPWM1B: U5.T14(GPMC_A3/GMII2_TXD2/RGMII2_TD2/MMC2_DAT2/GPMC_A19/PR1_MII1_TXD1/EHRPWM1B/GPIO1_19) ; also on sheet 6
EHRPWM2A: U5.U10(GPMC_AD8/LCD_DATA23/MMC1_DAT0/MMC2_DAT4/EHRPWM2A/PR1_MII_MT0_CLK//GPIO0_22) ; also on sheet 6
EHRPWM2B: U5.T10(GPMC_AD9/LCD_DATA22/MMC1_DAT1/MMC2_DAT5/EHRPWM2B/PR1_MII0_CRS//GPIO0_23) ; also on sheet 6
eMMC_RSTn: R162.2 ; also on sheet 5
ETH_RESETn: C27.1 R35.2 U1.4(Y) U14.19(nRST)
ETH_RST_GPIO1_8: R34.2 U1.1(A) U5.E18(UART0_CTSN/UART4_RXD/DCAN1_TX/I2C1_SDA/SPI1_D0/TIMER7/PR1_EDC_SYNC0_OUT/GPIO1_8)
ETH_TXD4: R145.1 U14.18(nINT/TXER/TXD4)
GPIO0_7: R50.1 R51.1 ; also on sheet 6
GPIO0_7SRC: R50.2 U5.C18(ECAP0_IN_PWM0_OUT/UART3_TXD/SPI1_CS1/PR1_ECAP0_ECAP_CAPIN_APWM_O/SPI1_SCLK/MMC0_SDWP/XDMA_EVENT_INTR2/GPIO0_7)
GPIO0_26: U5.T11(GPMC_AD10/LCD_DATA21/MMC1_DAT2/MMC2_DAT6/EHRPWM2_TRIPZONE_INPUT/PR1_MII0_TXEN//GPIO0_26) ; also on sheet 6
GPIO0_27: U5.U12(GPMC_AD11/LCD_DATA20/MMC1_DAT3/MMC2_DAT7/EHRPWM2_SYNCI_O/PR1_MII0_TXD3//GPIO0_27) ; also on sheet 6
GPIO1_12: U5.T12(GPMC_AD12/LCD_DATA19/MMC1_DAT4/MMC2_DAT0/EQEP2A_IN/PR1_MII0_TXD2/PR1_PRU0_PRU_R30_14/GPIO1_12) ; also on sheet 6
GPIO1_13: U5.R12(GPMC_AD13/LCD_DATA18/MMC1_DAT5/MMC2_DAT1/EQEP2B_IN/PR1_MII0_TXD1/PR1_PRU0_PRU_R30_15/GPIO1_13) ; also on sheet 6
GPIO1_14: U5.V13(GPMC_AD14/LCD_DATA17/MMC1_DAT6/MMC2_DAT2/EQEP2_INDEX/PR1_MII0_TXD0/PR1_PRU0_PRU_R31_14/GPIO1_14) ; also on sheet 6
GPIO1_15: U5.U13(GPMC_AD15/LCD_DATA16/MMC1_DAT7/MMC2_DAT3/EQEP2_STROBE/PR1_ECAP0_ECAP_CAPIN_APWM_O/PR1_PRU0_PRU_R31_15/GPIO1_15) ; also on sheet 6
GPIO1_16: R160.2 R161.2 ; also on sheet 6
GPIO1_17: U5.V14(GPMC_A1/GMII2_RXDV/RGMII2_RCTL/MMC2_DAT0/GPMC_A17/PR1_MII1_TXD3/EHRPWM1_SYNCI_O/GPIO1_17) ; also on sheet 6
GPIO1_28: U5.U18(GPMC_BE1N/GMII2_COL/GPMC_CSN6/MMC2_DAT3/GPMC_DIR/PR1_MII1_RXLINK/MCASP0_ACLKR/GPIO1_28) ; also on sheet 6
GPIO1_29: U5.V6(GPMC_CSN0/GPIO1_29) ; also on sheet 6
GPIO2_1: U5.V12(GPMC_CLK/LCD_MEM_CLK/GPMC_WAIT1/MMC2_CLK/PRT1_MII1_TXEN/MCASP0_FSR/GPIO2_1) ; also on sheet 6
GPIO3_18: R51.2 U5.B12(MCASP0_ACLKR/EQEP0A_IN/MCASP0_AXR2/MCASP1_ACLKX/MMC0_SDWP/PR1_PRU0_PRU_R30_4/PR1_PRU0_PRU_R31_4/GPIO3_18)
GPIO3_19: U5.C13(MCASP0_FSR/EQEP0B_IN/MCASP0_AXR3/MCASP1_FSX/EMU2/PR1_PRU0_PRU_R30_5/PR1_PRU0_PRU_R31_5/GPIO3_19) ; also on sheet 6
GPIO3_20: R20.2 U5.D13(MCASP0_AXR1/EQEP0_INDEX//MCASP1_AXR0/EMU3/PR1_PRU0_PRU_R30_6/PR1_PRU0_PRU_R31_6/GPIO3_20)
GPIO3_21: R167.2 U5.A14(MCASP0_AHCLKX/EQEP0_STROBE/MCASP0_AXR3/MCASP1_AXR1/EMU4/PR1_PRU0_PRU_R30_7/PR1_PRU0_PRU_R31_7/GPIO3_21) ; also on sheet 6
GRN_C: P5.10(GRNC) R132.2
GRNA: P5.9(GRNA) U14.3(LED1/REGOFF)
HDMI_INT: R169.1 R170.1 U5.U16(GPMC_A9/GMII2_RXD2/RGMII2_RD2/MMC2_DAT7/GPMC_A25/PR1_MII_MR1_CLK/MCASP0_FSX/GPIO1_25)
HDMICLK_DISn: U5.V17(GPMC_A11/GMII2_RXD0/RGMII2_RD0/RMII2_RXD0/GPMC_A27/PR1_MII1_RXER/MCASP0_AXR1/GPIO1_27) Y4.1(EN)
I2C0_SCL: U5.C16(I2C0_SCL/TIMER7/UART2_RTSN/ECAP1_IN_PWM1_OUT////GPIO3_6) ; also on sheet 2 6
I2C0_SDA: U5.C17(I2C0_SDA/TIMER4/UART2_CTSN/ECAP2_IN_PWM2_OUT////GPIO3_5) ; also on sheet 2 6
I2C1_SCL: U5.A16(SPI0_CS0/MMC2_SDWP/I2C1_SCL/EHRPWM0_SYNCI_O/PR1_UART0_TXD/PR1_EDIO_DATA_IN1/PR1_EDIO_DATA_OUT1/GPIO0_5) ; also on sheet 6
I2C1_SDA: U5.B16(SPI0_D1/MMC1_SDWP/I2C1_SDA/EHRPWM0_TRIPZONE_INPUT/PR1_UART0_RXD/PR1_EDIO_DATA_IN0/PR1_EDIO_DATA_OUT0/GPIO0_4) ; also on sheet 6
I2C2_SCL: U5.D17(UART1_RTSN/TIMER5/DCAN0_RX/I2C2_SCL/SPI1_CS1/PR1_UART0_RTS_N/PR1_EDC_LATCH1_IN/GPIO0_13) ; also on sheet 6
I2C2_SDA: U5.D18(UART1_CTSN/TIMER6/DCAN0_TX/I2C2_SDA/SPI1_CS0/PR1_UART0_CTS_N/PR1_EDC_LATCH0_IN/GPIO0_12) ; also on sheet 6
JTAG_EMU0: P2.13(EMU0) R23.2 U5.C14(EMU0/GPIO3_7)
JTAG_EMU1: P2.14(EMU1) R24.2 U5.B14(EMU1/GPIO3_8)
JTAG_TCK: P2.9(TCKRTN) P2.11(TCK) U5.A12(TCK)
JTAG_TDI: P2.3(TDI) U5.B11(TDI)
JTAG_TDO: P2.7(TDO) U5.A11(TDO)
JTAG_TMS: P2.1(TMS) U5.C11(TMS)
JTAG_TRSTn: P2.2(TRSTn) R25.1 U5.B10(NTRST)
LCD_DATA0: U5.R1(LCD_DATA0/GPMC_A0//EHRPWM2A//PR1_PRU1_PRU_R30_0/PR1_PRU1_PRU_R31_0/GPIO2_6) ; also on sheet 3 6
LCD_DATA1: U5.R2(LCD_DATA1/GPMC_A1//EHRPWM2B//PR1_PRU1_PRU_R30_1/PR1_PRU1_PRU_R31_1/GPIO2_7) ; also on sheet 3 6
LCD_DATA2: U5.R3(LCD_DATA2/GPMC_A2//EHRPWM2_TRIPZONE_INPUT//PR1_PRU1_PRU_R30_2/PR1_PRU1_PRU_R31_2/GPIO2_8) ; also on sheet 3 6
LCD_DATA3: U5.R4(LCD_DATA3/GPMC_A3//EHRPWM2_SYNCI_O//PR1_PRU1_PRU_R30_3/PR1_PRU1_PRU_R31_3/GPIO2_9) ; also on sheet 3 6
LCD_DATA4: U5.T1(LCD_DATA4/GPMC_A4//EQEP2A_IN//PR1_PRU1_PRU_R30_4/PR1_PRU1_PRU_R31_4/GPIO2_10) ; also on sheet 3 6
LCD_DATA5: U5.T2(LCD_DATA5/GPMC_A5//EQEP2B_IN//PR1_PRU1_PRU_R30_5/PR1_PRU1_PRU_R31_5/GPIO2_11) ; also on sheet 3 6
LCD_DATA6: U5.T3(LCD_DATA6/GPMC_A6/PR1_EDIO_DATA_IN6/EQEP2_INDEX/PR1_EDIO_DATA_OUT6/PR1_PRU1_PRU_R30_6/PR1_PRU1_PRU_R31_6/GPIO2_12) ; also on sheet 3 6
LCD_DATA7: U5.T4(LCD_DATA7/GPMC_A7/PR1_EDIO_DATA_IN7/EQEP2_STROBE/PR1_EDIO_DATA_OUT7/PR1_PRU1_PRU_R30_7/PR1_PRU1_PRU_R31_7/GPIO2_13) ; also on sheet 3 6
LCD_DATA8: U5.U1(LCD_DATA8/GPMC_A12/EHRPWM1_TRIPZONE_INPUT/MCASP0_ACLKX/UART5_TXD/PR1_MII0_RXD3/UART2_CTSN/GPIO2_14) ; also on sheet 3 6
LCD_DATA9: U5.U2(LCD_DATA9/GPMC_A13/EHRPWM1_SYNCI_O/MCASP0_FSX/UART5_RXD/PR1_MII0_RXD2/UART2_RTSN/GPIO2_15) ; also on sheet 3 6
LCD_DATA10: U5.U3(LCD_DATA10/GPMC_A14/EHRPWM1A/MCASP0_AXR0//PR1_MII0_RXD1/UART3_CTSN/GPIO2_16) ; also on sheet 3 6
LCD_DATA11: U5.U4(LCD_DATA11/GPMC_A15/EHRPWM1B/MCASP0_AHCLKR/MCASP0_AXR2/PR1_MII0_RXD0/UART3_RTSN/GPIO2_17) ; also on sheet 3 6
LCD_DATA12: U5.V2(LCD_DATA12/GPMC_A16/EQEP1A_IN/MCASP0_ACLKR/MCASP0_AXR2/PR1_MII0_RXLINK/UART4_CTSN/GPIO0_8) ; also on sheet 3 6
LCD_DATA13: U5.V3(LCD_DATA13/GPMC_A17/EQEP1B_IN/MCASP0_FSR/MCASP0_AXR3/PR1_MII0_RXER/UART4_RTSN/GPIO0_9) ; also on sheet 3 6
LCD_DATA14: U5.V4(LCD_DATA14/GPMC_A18/EQEP1_INDEX/MCASP0_AXR1/UART5_RXD/PR1_MII_MR0_CLK/UART5_CTSN/GPIO0_10) ; also on sheet 3 6
LCD_DATA15: U5.T5(LCD_DATA15/GPMC_A19/EQEP1_STROBE/MCASP0_AHCLKX/MCASP0_AXR3/PR1_MII0_RXDV/UART5_RTSN/GPIO0_11) ; also on sheet 3 6
LCD_DE: R48.2 ; also on sheet 6
LCD_HSYNC: R47.2 ; also on sheet 6
LCD_PCLK: R45.2 ; also on sheet 6
LCD_VSYNC: R46.2 ; also on sheet 6
LCDDE: R48.1 U5.R6(LCD_AC_BIAS_EN/GPMC_A11//PR1_EDIO_DATA_IN5/PR1_EDIO_DATA_OUT5/PR1_PRU1_PRU_R30_11/PR1_PRU1_PRU_R31_11/GPIO2_25)
LCDPCLK: R45.1 U5.V5(LCD_PCLK/GPMC_A10//PR1_EDIO_DATA_IN4/PR1_EDIO_DATA_OUT4/PR1_PRU1_PRU_R30_10/PR1_PRU1_PRU_R31_10/GPIO2_24)
LCDVHYNC: R47.1 U5.R5(LCD_HSYNC/GPMC_A9//PR1_EDIO_DATA_IN3/PR1_EDIO_DATA_OUT3/PR1_PRU1_PRU_R30_9/PR1_PRU1_PRU_R31_9/GPIO2_23)
LCDVSYNC: R46.1 U5.U5(LCD_VSYNC/GPMC_A8//PR1_EDIO_DATA_IN2/PR1_EDIO_DATA_OUT2/PR1_PRU1_PRU_R30_8/PR1_PRU1_PRU_R31_8/GPIO2_22)
LDO_PGOOD: U5.B5(RTC_PORZn) ; also on sheet 2
MDIO_CLK: U5.M18(MDIO_CLK/TIMER5/UART5_TXD/UART3_RTSN/MMC0_SDWP/MMC1_CLK/MMC2_CLK/GPIO0_1) U14.17(MDC)
MDIO_DATA: R119.2 U5.M17(MDIO_DATA/TIMER6/UART5_RXD/UART3_CTSN/MMC0_SDCD/MMC1_CMD/MMC2_CMD/GPIO0_0) U14.16(MDIO)
MII1_COL: R138.1 U5.H16(GMII1_COL/RMII2_REFCLK/SPI1_SCLK/UART5_RXD/MCASP1_AXR2/MMC2_DAT3/MCASP0_AXR2/GPIO3_0)
MII1_CRS_DV: R139.1 U5.H17(GMII1_CRS/RMII1_CRS_DV/SPI1_D0/I2C1_SDA/MCASP1_ACLKX/UART5_CTSN/UART2_RXD/GPIO3_1)
MII1_REFCLK: R28.2 R124.1 R140.1
MII1_RXCLK: R131.1 U5.L18(GMII1_RXCLK/UART2_TXD/RGMII1_RCLK/MMC0_DAT6/MMC1_DAT1/UART1_DSRN/MCASP0_FSX/GPIO3_10)
MII1_RXD0: R128.1 U5.M16(GMII1_RXD0/RMII1_RXD0/RGMII1_RD0/MCASP1_AHCLKX/MCASP1_AHCLKR/MCASP1_ACLKR/MCASP0_AXR3/GPIO2_21)
MII1_RXD1: R127.1 U5.L15(GMII1_RXD1/RMII1_RXD1/RGMII1_RD1/MCASP1_AXR3/MCASP1_FSR/EQEP0_STROBE/MMC2_CLK/GPIO2_20)
MII1_RXD2: R126.1 U5.L16(GMII1_RXD2/UART3_TXD/RGMII1_RD2/MMC0_DAT4/MMC1_DAT3/UART1_RIN/MCASP0_AXR1/GPIO2_19)
MII1_RXD3: R125.1 U5.L17(GMII1_RXD3/UART3_RXD/RGMII1_RD3/MMC0_DAT5/MMC1_DAT2/UART1_DTRN/MCASP0_AXR0/GPIO2_18)
MII1_RXDV: R129.1 U5.J17(GMII1_RXDV/LCD_MEMORY_CLK/RGMII1_RCTL/UART5_TXD/MCASP1_ACLKX/MMC2_DAT0/MCASP0_ACLKR/GPIO3_4)
MII1_RXERR: R133.1 U5.J15(GMII1_RXERR/RMII1_RXERR/SPI1_D1/I2C1_SCL/MCASP1_FSX/UART5_RTSN/UART2_TXD/GPIO3_2)
MII1_TXCLK: R134.1 U5.K18(GMII1_TXCLK/UART2_RXD/RGMII1_TCLK/MMC0_DAT7/MMC1_DAT0/UART1_DCDN/MCASP0_ACLKX/GPIO3_9)
MII1_TXD0: R158.1 U5.K17(GMII1_TXD0/RMII1_TXD0/RGMII1_TD0/MCASP1_AXR2/MCASP1_ACLKR/EQEP0B_IN/MMC1_CLK/GPIO0_28)
MII1_TXD1: R166.1 U5.K16(GMII1_TXD1/RMII1_TXD1/RGMII1_TD1/MCASP1_FSR/MCASP1_AXR1/EQEP0A_IN/MMC1_CMD/GPIO0_21)
MII1_TXD2: R171.1 U5.K15(GMII1_TXD2/DCAN0_RX/RGMII1_TD2/UART4_TXD/MCASP1_AXR0/MMC2_DAT2/MCASP0_AHCLKX/GPIO0_17)
MII1_TXD3: R172.1 U5.J18(GMII1_TXD3/DCAN0_TX/RGMII1_TD3/UART4_RXD/MCASP1_FSX/MMC2_DAT1/MCASP0_FSR/GPIO0_16)
MII1_TXEN: R149.1 U5.J16(GMII1_TXEN/RMII1_TXEN/RGMII1_TCTL/TIMER4/MCASP1_AXR0/EQEP0_INDEX/MMC2_CMD/GPIO3_3)
MMC0_CD: P2.19(EMU4) U5.C15(SPI0_CS1/UART3_RXD/ECAP1_IN_PWM1_OUT/MMC0_POW/XDMA_EVENT_INTR2/MMC0_SDCD/EMU4/GPIO0_6) ; also on sheet 6
MMC0_CLKO: U5.G17(MMC0_CLK/GPMC_A24/UART3_CTSN/UART2_RXD/DCAN1_TX/PR1_PRU0_PRU_R30_12/PR1_PRU0_PRU_R31_12/GPIO2_30) ; also on sheet 6
MMC0_CMD: U5.G18(MMC0_CMD/GPMC_A25/UART3_RTSN/UART2_TXD/DCAN1_RX/PR1_PRU0_PRU_R30_13/PR1_PRU0_PRU_R31_13/GPIO2_31) ; also on sheet 6
MMC0_DAT0: U5.G16(MMC0_DAT0/GPMC_A23/UART5_RTSN/UART3_TXD/UART1_RIN/PR1_PRU0_PRU_R30_11/PR1_PRU0_PRU_R31_11/GPIO2_29) ; also on sheet 6
MMC0_DAT1: U5.G15(MMC0_DAT1/GPMC_A22/UART5_CTSN/UART3_RXD/UART1_DTRN/PR1_PRU0_PRU_R30_10/PR1_PRU0_PRU_R31_10/GPIO2_28) ; also on sheet 6
MMC0_DAT2: U5.F18(MMC0_DAT2/GPMC_A21/UART4_RTSN/TIMER6/UART1_DSRN/PR1_PRU0_PRU_R30_9/PR1_PRU0_PRU_R31_9/GPIO2_27) ; also on sheet 6
MMC0_DAT3: U5.F17(MMC0_DAT3/GPMC_A20/UART4_CTSN/TIMER5/UART1_DCDN/PR1_PRU0_PRU_R30_8/PR1_PRU0_PRU_R31_8/GPIO2_26) ; also on sheet 6
MMC1_CLK: C6.1 R32.2 ; also on sheet 5 6
MMC1_CMD: R33.2 ; also on sheet 5 6
MMC1_DAT0: R37.2 ; also on sheet 5 6
MMC1_DAT1: R38.2 ; also on sheet 5 6
MMC1_DAT2: R39.2 ; also on sheet 5 6
MMC1_DAT3: R40.2 ; also on sheet 5 6
MMC1_DAT4: R41.2 ; also on sheet 5 6
MMC1_DAT5: R42.2 ; also on sheet 5 6
MMC1_DAT6: R43.2 ; also on sheet 5 6
MMC1_DAT7: R44.2 ; also on sheet 5 6
MODE2: R113.1 R138.2 U14.15(COL/CRS_DV/MODE2)
OSC0_IN: C25.1 R17.1 U5.V10(OSC0_IN) Y2.1
OSC0_OUT: R17.2 R179.1 U5.U11(OSC0_OUT)
OSC1_IN: C21.2 U5.A6(OSC1_IN) Y1.2
OSC1_OUT: C22.2 U5.A4(OSC1_OUT) Y1.1
PHY_VDDCR: C134.1 C136.1 U14.6(VDDCR)
PHY_XTAL1: C143.1 R141.2 R142.1 Y3.3
PHY_XTAL2: R141.1 R143.2 U14.4(XTAL2)
PHYX: C142.1 R143.1 Y3.1
PMIC_INT: U5.B18(NNMI) ; also on sheet 2
PMIC_PGOOD: U5.B15(PORZn) U16.2(A) ; also on sheet 2
PMIC_POWR_EN: U5.C6(PMIC_POWER_EN) ; also on sheet 2
PROC_A15: R18.1 U5.A15(EVENT_INTR0/TIMER4/CLKOUT1/SPI1_CS1/PR1PRU1R31_16/EMU2/GPIO0_19)
RBIAS: R144.1 U14.32(RBIAS)
RCLKIN: R140.2 R142.2 U14.5(XTAL1/CLKIN)
REFCLKO: R118.1 R124.2 R131.2 U14.7(RXCLK/PHYAD1)
RXD0/MODE0: R112.1 R128.2 U14.11(RXD0/MODE0)
RXD1/MODE1: R114.1 R127.2 U14.10(RXD1/MODE1)
RXD2/RMIISEL: R117.1 R126.2 U14.9(RXD2/RMIISEL)
RXD3/PHYAD2: R116.1 R125.2 U14.8(RXD3/PHYAD2)
RXDV: R129.2 U14.26(RXDV)
RXER/PHYAD0: R115.1 R133.2 U14.13(RXER/RXD4/PHYAD0)
RXN: C138.1 P5.2(RD-) R121.1 U14.30(RXN)
RXP: C137.1 P5.1(RD+) R120.1 U14.31(RXP)
SPI1_CS0: U5.C12(MCASP0_AHCLKR/EHRPWM0_SYNCI_O/MCASP0_AXR2/SPI1_CS0/ECAP2_IN_PWM2_OUT/PR1_PRU0_PRU_R30_3/PR1_PRU0_PRU_R31_3/GPIO3_17) ; also on sheet 6
SPI1_D0: U5.B13(MCASP0_FSX/EHRPWM0B//SPI1_D0/MMC1_SDCD/PR1_PRU0_PRU_R30_1/PR1_PRU0_PRU_R31_1/GPIO3_15) ; also on sheet 6
SPI1_D1: U5.D12(MCASP0_AXR0/EHRPWM0_TRIPZONE_INPUT//SPI1_D1/MMC2_SDCD/PR1_PRU0_PRU_R30_2/PR1_PRU0_PRU_R31_2/GPIO3_16) ; also on sheet 6
SPI1_SCLK: U5.A13(MCASP0_ACLKX/EHRPWM0A//SPI1_SCLK/MMC0_SDCD/PR1_PRU0_PRU_R30_0/PR1_PRU0_PRU_R31_0/GPIO3_14) ; also on sheet 6
SYS_5V: C34.1 U8.2(IN1) U8.3(IN2) ; also on sheet 2 3 6
SYS_RESETn: C24.1 C30.1 D6.2 D7.2 P2.15(SRST) R14.2 R148.1 S1.2(B1) S1.4(B2) U5.A10(NRESET_INOUT) U6.2(A) U16.4(Y) ; also on sheet 6
TCT_RCT: C141.1 P5.4(RCT) P5.5(TCT) R137.1
TIMER4: U5.R7(GPMC_ADVN_ALE/TIMER4/GPIO2_2) ; also on sheet 6
TIMER5: U5.T6(GPMC_BE0N_CLE/TIMER5/GPIO2_5) ; also on sheet 6
TIMER6: U5.U6(GPMC_WEN/TIMER6/GPIO2_4) ; also on sheet 6
TIMER7: U5.T7(GPMC_OEN_REN/TIMER7/EMU4/GPIO2_3) ; also on sheet 6
TXCLK: R134.2 U14.20(TXCLK)
TXD0: R158.2 U14.22(TXD0)
TXD1: R166.2 U14.23(TXD1)
TXD2: R171.2 U14.24(TXD2)
TXD3: R172.2 U14.25(TXD3)
TXEN: R149.2 U14.21(TXEN)
TXN: C140.1 P5.6(TD-) R123.1 U14.28(TXN)
TXP: C139.1 P5.3(TD+) R122.1 U14.29(TXP)
U5_H18: R28.1 U5.H18(RMII1_REFCLK/XDMA_EVENT_INTR2/SPI1_CS0/UART5_TXD/MCASP1_AXR3/MMC0_POW/MCASP1_AHCLKX/GPIO0_29)
U5_R13: R160.1 U5.R13(GPMC_A0/GMII2_TXEN/RGMII2_TCTL/RMII2_TXEN/GPMC_A16/PR1_MII_MT1_CLK/EHRPWM1_TRIPZONE_INPUT/GPIO1_16)
U5_T13: R161.1 U5.T13(GPMC_CSN3/MMC2_CMD/PR1_MDIO_DATA/GPIO2_0)
UART0_RX: U5.E15(UART0_RXD/SPI1_CS0/DCAN0_TX/I2C2_SDA/ECAP2_IN_PWM2_OUT/PR1_PRU1_PRU_R30_14/PR1_PRU1_PRU_R31_14/GPIO1_10) U15.6(1Y)
UART0_TX: U5.E16(UART0_TXD/SPI1_CS1/DCAN0_RX/I2C2_SCL/ECAP1_IN_PWM1_OUT/PR1_PRU1_PRU_R30_15/PR1_PRU1_PRU_R31_15/GPIO1_11) U15.5(2A)
UART1_RXD: U5.D16(UART1_RXD/MMC1_SDWP/DCAN1_TX/I2C1_SDA//PR1_UART0_RXD/PR1_PRU1_PRU_R31_16/GPIO0_14) ; also on sheet 6
UART1_TXD: U5.D15(UART1_TXD/MMC2_SDWP/DCAN1_RX/I2C1_SCL//PR1_UART0_TXD/PR1_PRU0_PRU_R31_16/GPIO0_15) ; also on sheet 6
UART2_RXD: U5.A17(SPI0_SCLK/UART2_RXD/I2C2_SDA/EHRPWM0A/PR1_UART0_CTS_N/PR1_EDIO_SOF/EMU2/GPIO0_2) ; also on sheet 6
UART2_TXD: U5.B17(SPI0_D0/UART2_TXD/I2C2_SCL/EHRPWM0B/PR1_UART0_RTS_N/PR1_EDIO_LATCH_IN/EMU3/GPIO0_3) ; also on sheet 6
UART4_RXD: U5.T17(GPMC_WAIT0/GM112_CRS/GPMC_CSN4/RMII2_CRS_DV/MMC1_SDCD/PR1_MII1_RXDV/UART4_RXD/GPIO0_30) ; also on sheet 6
UART4_TXD: U5.U17(GPMC_WPN/GMII2_RXERR/GPMC_CSN5/RMII2_RXERR/MMC2_SDCD/PR1_MDIO_MDCLK/UART4_TXD/GPIO0_31) ; also on sheet 6
USB0_DM: P4.2(D-) U5.N18(USB0_DM) U10.2(D-)
USB0_DP: P4.3(D+) U5.N17(USB0_DP) U10.1(D+)
USB0_ID: P4.4(ID) U5.P16(USB0_ID) U10.3(ID)
USB1_DM: P3.2(P2) U5.R18(USB1_DM) U9.2(D-)
USB1_DP: P3.3(P3) U5.R17(USB1_DP) U9.1(D+)
USB1_DRVVBUS: R53.1 U5.F15(USB1_DRVVBUS/GPIO3_13) U8.4(EN)
USB1_ID: R49.2 U5.P17(USB1_ID)
USB1_OCn: R52.2 U5.T16(GPMC_A10/GMII2_RXD1/RGMII2_RD1/RMII2_RXD1/GPMC_A26/PR1_MII1_CRS/MCASP0_AXR0/GPIO1_26) U8.5(~{OC})
USB1_PWR: C35.1 FB7.1 R36.2 U8.6(OUT3) U8.7(OUT2) U8.8(OUT1) U9.6(VBUS)
USB1_VBUS: R36.1 U5.T18(USB1_VBUS)
USB_DC: C36.1 P4.1(VB) R159.1 U10.6(VBUS) ; also on sheet 2
USR0: U5.V15(GPMC_A5/GMII2_TXD0/RGMII2_TD0/RMII2_TXD0/GPMC_A21/PR1_MII1_RXD3/EQEP1B_IN/GPIO1_21) ; also on sheet 3
USR1: U5.U15(GPMC_A6/GMII2_TXCLK/RGMII2_TCLK/MMC2_DAT4/GPMC_A22/PR1_MII1_RXD2/EQEP1_INDEX/GPIO1_22) ; also on sheet 3
USR2: U5.T15(GPMC_A7/GMII2_RXCLK/RGMII2_RCLK/MMC2_DAT5/GPMC_A23/PR1_MII1_RXD1/EQEP1_STROBE/GPIO1_23) ; also on sheet 3
USR3: U5.V16(GPMC_A8/GMII2_RXD3/RGMII2_RD3/MMC2_DAT6/GPMC_A24/PR1_MII1_RXD0/MCASP0_ACLKX/GPIO1_24) ; also on sheet 3
VIO: U16.5(VCC) ; also on sheet 2
VREFP_ADC: C31.1 C32.1 C33.1 R27.2 U5.B9(VREFP)
VRTC: R26.1 ; also on sheet 2 7
WAKEUP: R26.2 U5.C5(EXT_WAKEUP) ; also on sheet 2
XDMA_EVENT_INTR0: P2.17(EMU2) R18.2
YEL_C: P5.11(YELC) R130.2
YELA: P5.12(YELA) R135.1 U14.2(LED2/nINTSEL)
N22155575: R159.2 U5.P15(USB0_VBUS)
N22287501: R162.1 U3.4(Y)
N22287555: U3.2(A) U5.R14(GPMC_A4/GMII2_TXD1/RGMII2_TD1/RMII2_TXD1/GPMC_A20/PR1_MII1_TXD0/EQEP1A_IN/GPIO1_20)
N22488252: TP9.1(TP) U5.E17(UART0_RTSN/UART4_TXD/DCAN1_RX/I2C1_SCL/SPI1_D1/SPI1_CS0/PR1_EDC_SYNC1_OUT/GPIO1_9)
N22710186: R32.1 U5.U9(GPMC_CSN1/GPMC_CLK/MMC1_CLK/PRT1EDIO_DATA_IN6/PRT1_EDIO_DATA_OUT6/PR1_PRU1_PRU_R30_12/PR1_PRU1_PRU_R31_12/GPIO1_30)
N22710189: R33.1 U5.V9(GPMC_CSN2/GPMC_BE1N/MMC1_CMD/PR1_EDIO_DATA_IN7/PR1_EDIO_DATA_OUT7/PR1_PRU1_PRU_R30_13/PR1_PRU1_PRU_R31_13/GPIO1_31)
N22740401: C145.1 R148.2 U1.2(B) U6.4(Y)
N22872429: C26.1 R179.2 Y2.3
N22916735: R167.1 Y4.3(CLK)

Not connected (* = marked no-connect by the designer): J1 2* 3* 6*; P2 6(NC)*; P5 7(NC)*; U3 1(NC)*; U5 F16(USB0_DRVVBUS/GPIO0_18) M15(USB0_CE) P18(USB1_CE); U6 1(NC)*; U9 3(ID)* 5(NC)*; U10 5(NC)*; U16 1(NC)*

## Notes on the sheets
sheet 8
- ETHERNET
  CONNECTOR
- ESD_RING
- ACTIVE WHEN LINK PRESENT.
  BLINKS OFF DURING ACTIVITY.
- ACTIVE WHEN AT 100MB
sheet 9
- Mark pin 1
  clearly
- UART0 Serial
  Port
- POWERDOWN
  ISOLATION
- USB to TTL
  Serial Cable
  3.3V
- USB PC
  CONNECTOR
- USB HOST
sheet 10
- 3.3V
- RESET
- 1.8V
- 1.8V
- 3.3V
- Layout Note:
- Place R32,R33,C6 Close To MPU.
- H
- External
  clock to the
  McASP0
  interface.
- Oscillator can be disabled
  via SW for power down
  modes or if GPIO3_21
  needs to be used.
